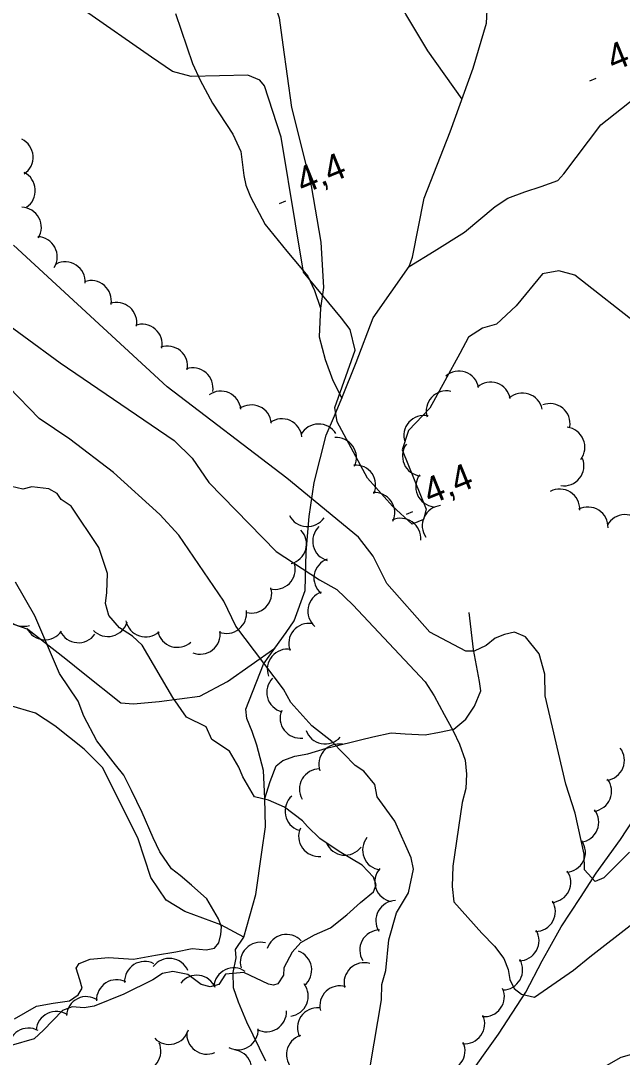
# Model space of a CAD drawing. Extents: x 362852 to 366875, y 5563573 to 5566479.
# Drawn here: x 364068.7 to 364158.5, y 5565324.6 to 5565479.3 of the extents above; entities that cross this region are included whole.
import ezdxf

# ---------------------------------------------------------------- set-up
doc = ezdxf.new("R2010")
doc.units = 0
for name, color, linetype in [('Niveau 1', 7, 'Continuous'), ('Niveau 2', 7, 'Continuous'), ('Niveau 22', 7, 'Continuous'), ('Niveau 3', 7, 'Continuous'), ('Niveau 44', 7, 'Continuous'), ('Niveau 7', 7, 'Continuous')]:
    doc.layers.add(name, color=color, linetype=linetype)

msp = doc.modelspace()

# ---------------------------------------------------------------- linework, layer by layer
at = {"layer": 'Niveau 1'}
for points in [[(364120.92, 5565323.43), (364122.56, 5565333.11), (364122.6, 5565335.4), (364123.21, 5565337.53), (364123.67, 5565342.07), (364124.81, 5565346.1), (364126.58, 5565349.09), (364127.32, 5565352.65), (364127, 5565354.32), (364124.54, 5565359.8), (364121.92, 5565363.44), (364121.55, 5565365.26), (364119.93, 5565367.25), (364118.62, 5565368.14), (364115.12, 5565371.7), (364112.17, 5565374.03), (364109.04, 5565377.53), (364107.94, 5565379.52), (364100.83, 5565388.92), (364099.05, 5565392.64), (364092.32, 5565402.51), (364089.49, 5565405.58), (364082.59, 5565411.87), (364076.04, 5565416.85), (364071.46, 5565419.94), (364066.94, 5565424.63)], [(364124.41, 5565287.96), (364124.93, 5565289.57), (364126.67, 5565294.45), (364127.91, 5565296.91), (364129.36, 5565298.57), (364130.31, 5565299.55), (364133.54, 5565305.42), (364135.12, 5565307.27), (364138.92, 5565309.96), (364142.25, 5565311.27), (364144.51, 5565313.16), (364146.81, 5565314.36), (364147.72, 5565315.51), (364148.63, 5565315.94), (364152.51, 5565320.76), (364153.91, 5565322.06), (364158.31, 5565324.57), (364165.11, 5565326.53)]]:
    msp.add_lwpolyline(points, dxfattribs=at)
at = {"layer": 'Niveau 2'}
for points in [[(364159.55, 5565355.17), (364155.73, 5565351.34), (364154.44, 5565350.81), (364152.86, 5565352.55), (364152.79, 5565354.9), (364151.44, 5565361), (364150.06, 5565365.33), (364146.98, 5565378.5), (364146.92, 5565381.74), (364146.07, 5565384.78), (364144.03, 5565387.34), (364142.38, 5565388.04), (364140.9, 5565387.68), (364139.5, 5565387.11), (364138.18, 5565386.06), (364136.4, 5565385.21), (364135.15, 5565385.2), (364129.77, 5565388.01), (364123.33, 5565395.29), (364121.3, 5565399.36), (364119.14, 5565402.23), (364108.45, 5565411.04), (364090.56, 5565424.67), (364067.63, 5565445.8)], [(364063.74, 5565436.2), (364074.59, 5565428.23), (364091.63, 5565416.66), (364094.32, 5565414), (364096.79, 5565410.37), (364106.83, 5565400.07), (364113.29, 5565395.82), (364115.87, 5565394.38), (364118.28, 5565392.11), (364129.05, 5565380.6), (364130.39, 5565378.52), (364131.89, 5565375.75), (364133.25, 5565373.3), (364134.19, 5565371.3), (364135.04, 5565368.9), (364135.24, 5565366.85), (364135.13, 5565364.67), (364134.6, 5565362.57), (364133.2, 5565353.1), (364133.07, 5565350.04), (364133.36, 5565347.78), (364137.5, 5565343.09), (364139.42, 5565341.12), (364140.78, 5565339.3), (364141.43, 5565337.68), (364141.68, 5565336.16), (364142.35, 5565334.8), (364143.43, 5565333.99), (364145.36, 5565333.53), (364151.21, 5565337.56), (364153.64, 5565339.56), (364160.09, 5565344.59)], [(364083.46, 5565388.67), (364081.89, 5565390.51), (364081.38, 5565392.29), (364081.59, 5565393.94), (364081.67, 5565396.78), (364080.37, 5565400.65), (364076.27, 5565406.86), (364074.77, 5565407.85), (364074.15, 5565408.72), (364072.92, 5565409.42), (364070.36, 5565409.75), (364069.04, 5565409.37), (364067.34, 5565409.76), (364057.49, 5565421.38)], [(364067.8, 5565330.28), (364071.07, 5565332.18), (364073.55, 5565332.64), (364076.02, 5565332.97), (364077.28, 5565333.86), (364077.87, 5565334.85), (364077.53, 5565336.14), (364077.02, 5565337.87), (364077.43, 5565338.54), (364079.08, 5565339.21), (364081.83, 5565339.47), (364085.54, 5565339.19), (364088.84, 5565339.79), (364091.86, 5565340.28), (364094.32, 5565340.79), (364096.39, 5565340.58), (364097.65, 5565340.85), (364098.26, 5565341.66), (364098.56, 5565342.91), (364098.67, 5565344.01), (364098.24, 5565345.21), (364096.47, 5565348.22), (364094.22, 5565350.23), (364092.51, 5565351.71), (364091.24, 5565352.69), (364089.48, 5565355.21), (364088.5, 5565357.3), (364086.84, 5565361.11), (364085.26, 5565364.39), (364084.09, 5565366.66), (364082.86, 5565368.2), (364080.07, 5565371.8), (364078.12, 5565375.48), (364077.3, 5565377.71), (364074.52, 5565381.84), (364070.82, 5565390.47), (364067.95, 5565395.47)], [(364109.21, 5565340.25), (364110.52, 5565341.68), (364112.54, 5565342.83), (364114.92, 5565343.86), (364117.36, 5565345.81), (364119.42, 5565347.65), (364121.37, 5565349.26), (364121.76, 5565350.3), (364121.36, 5565351.44), (364119.69, 5565353.26), (364116.26, 5565355.28), (364113.36, 5565357.22), (364111.52, 5565359.02), (364110.79, 5565359.88), (364108.09, 5565361.92), (364105.67, 5565362.96), (364103.59, 5565363.44), (364101.85, 5565366.45), (364101.28, 5565367.87), (364099.86, 5565370.28), (364097.26, 5565372.02), (364096.38, 5565373.88), (364093.48, 5565375.34), (364091.4, 5565378.25), (364086.86, 5565386.11), (364085.4, 5565387.45), (364083.46, 5565388.67)], [(364109.21, 5565340.25), (364107.99, 5565337.89), (364107.94, 5565336.81), (364107.08, 5565335.52), (364106.43, 5565335.33), (364105.69, 5565335.47), (364102.01, 5565337.23), (364099.26, 5565336.96), (364098.3, 5565335.44), (364096.99, 5565335.07), (364095.66, 5565335.4), (364093.65, 5565336.93), (364091.42, 5565337.35), (364089.9, 5565337.07), (364088.43, 5565336.13), (364084.1, 5565333.98), (364079.7, 5565332.19), (364078.19, 5565331.94), (364076.39, 5565332.11), (364074.96, 5565331.53), (364072.13, 5565328.6), (364070.73, 5565327.3), (364067.31, 5565326.31)]]:
    msp.add_lwpolyline(points, dxfattribs=at)
at = {"layer": 'Niveau 22'}
for points in [[(364134.57, 5565467.62), (364129.45, 5565474.84), (364126.18, 5565480.29), (364120.27, 5565490.7), (364114.99, 5565497.09), (364112.39, 5565501.63), (364107.86, 5565511.42), (364102.92, 5565525.77), (364101.49, 5565533.31), (364101.83, 5565535.72), (364103.26, 5565542.86), (364103.01, 5565544.27), (364101.37, 5565550.35), (364100.43, 5565554.69), (364100.77, 5565556.78), (364101.53, 5565558.8), (364102.86, 5565563.69), (364102.91, 5565565.1), (364103.94, 5565566.91), (364108.75, 5565573.3), (364113.88, 5565584.31), (364114.87, 5565586.27)], [(364076.01, 5565570.5), (364075.83, 5565567.1), (364076.49, 5565560.05), (364078.35, 5565552.24), (364079.56, 5565545.67), (364081.42, 5565537.86), (364083.93, 5565532.08), (364086.33, 5565528.03), (364089.46, 5565519.54), (364092.91, 5565510.88), (364098.61, 5565499.93), (364104.42, 5565488.53), (364107.28, 5565479.75), (364107.85, 5565475.71), (364109.14, 5565466.36), (364112.07, 5565454.65), (364113.52, 5565446.25), (364113.89, 5565439.48), (364113.44, 5565436.4), (364113.34, 5565434.35), (364113.24, 5565432.11), (364114.15, 5565428.76), (364115.31, 5565425.58), (364116.62, 5565422.98)], [(364105.31, 5565323.98), (364102.45, 5565329.81), (364101.23, 5565332.79), (364100.49, 5565334.92), (364100.4, 5565337.23), (364100.87, 5565339.4), (364100.78, 5565340.64), (364102, 5565342.5), (364103.79, 5565348.88), (364104.7, 5565355.18), (364105.23, 5565358.97), (364105.13, 5565363.17), (364104.95, 5565367.37), (364103.97, 5565371.17), (364103.27, 5565373.18), (364102.46, 5565375.16), (364102.33, 5565376.53), (364104.96, 5565383.24), (364106.65, 5565385.62), (364108.35, 5565388), (364109.51, 5565389.73), (364111.16, 5565394.24), (364111.29, 5565399.99), (364111.76, 5565405.28), (364112.51, 5565410.39), (364114.3, 5565417.46), (364115.54, 5565420.31), (364116.62, 5565422.98), (364118.76, 5565428.31), (364121.32, 5565434.96), (364126.67, 5565442.63), (364127.17, 5565444.03), (364128.94, 5565452.82), (364132.81, 5565462.71), (364136.23, 5565472.24), (364138.2, 5565478.97), (364138.69, 5565488.74)], [(364126.67, 5565442.63), (364130.43, 5565444.93), (364134.94, 5565447.73), (364139.52, 5565451.56), (364141.39, 5565452.83), (364143.95, 5565453.76), (364146.38, 5565454.57), (364148.84, 5565455.45), (364149.74, 5565456.46), (364155.25, 5565463.76), (364160.5, 5565467.93), (364167.05, 5565471.56), (364168.87, 5565472.52), (364174.36, 5565475.98), (364175.69, 5565478.41), (364178.22, 5565483.29)], [(364091.81, 5565480.39), (364094.33, 5565472.93), (364095.52, 5565470.45), (364097.36, 5565466.99), (364100.36, 5565462.38), (364101.59, 5565459.8), (364101.99, 5565456.19), (364102.32, 5565454.75), (364103.02, 5565453.02), (364105.2, 5565448.88), (364108.43, 5565444.92), (364111.58, 5565441.19), (364112.58, 5565439.02), (364113.44, 5565436.4)], [(364062.02, 5565391.16), (364069.78, 5565388.46), (364075.46, 5565384.06), (364078.05, 5565381.97), (364083.66, 5565377.49), (364085.53, 5565377.35), (364089.37, 5565377.69), (364095.46, 5565378.47), (364099.58, 5565380.64), (364106.65, 5565385.62)], [(364105.13, 5565363.17), (364105.93, 5565365.71), (364106.82, 5565368.07), (364107.82, 5565368.88), (364109.64, 5565369.52), (364111.55, 5565369.87), (364114.33, 5565370.7), (364115.2, 5565370.89), (364119.44, 5565371.93), (364121.27, 5565372.39), (364123.97, 5565373.02), (364126.06, 5565372.84), (364129.06, 5565372.72), (364131.21, 5565373.08), (364133.32, 5565373.56), (364135.11, 5565375.06), (364136.44, 5565376.98), (364137.37, 5565379.28), (364137.15, 5565380.66), (364136.28, 5565385.43), (364135.63, 5565390.98)], [(364102, 5565342.5), (364098.58, 5565344.33), (364093.21, 5565346.34), (364090.43, 5565348.02), (364088.15, 5565351.4), (364086.25, 5565357.16), (364080.96, 5565367.78), (364078.21, 5565370.58), (364073.8, 5565374.03), (364070.94, 5565375.93), (364064.16, 5565377.9), (364060.41, 5565379.01), (364057.36, 5565381.16), (364054.49, 5565384.6), (364051.69, 5565388.65)], [(364104.64, 5565289.11), (364110.21, 5565293.57), (364116.31, 5565298.95), (364118.78, 5565301.52), (364122.36, 5565305.25), (364128.68, 5565313.54), (364134.91, 5565320.89), (364140.03, 5565327.99), (364144.1, 5565334.29), (364146.51, 5565338.94), (364147.4, 5565340.54), (364149.36, 5565344.04), (364152.24, 5565348.43), (364154.57, 5565352.03), (364158.2, 5565357.05), (364163.11, 5565364.61)]]:
    msp.add_lwpolyline(points, dxfattribs=at)
at = {"layer": 'Niveau 3'}
for p, q in [((364153.64, 5565470.37), (364154.6, 5565470.76)), ((364107.31, 5565452.03), (364108.27, 5565452.42)), ((364126.26, 5565405.65), (364127.22, 5565406.04))]:
    msp.add_line(p, q, dxfattribs=at)
at = {"layer": 'Niveau 44'}
for centre, start, end in [((364067.57, 5565458.95), 303.8962, 63.8742), ((364067.91, 5565453.96), 303.8962, 63.8742), ((364068.81, 5565448.47), 328.3589, 88.3369), ((364071.18, 5565444.07), 328.3589, 88.3369), ((364075.35, 5565440.32), 356.8135, 116.7915), ((364079.25, 5565437.52), 349.3105, 109.2884), ((364083.04, 5565434.26), 349.3105, 109.2884), ((364086.83, 5565431), 349.3105, 109.2884), ((364090.62, 5565427.74), 349.4935, 109.4714), ((364094.42, 5565424.49), 349.4935, 109.4714), ((364134.1, 5565424), 10.8423, 130.8203), ((364138.82, 5565422.36), 10.8423, 130.8203), ((364098.58, 5565421.02), 5.5854, 125.5634), ((364132.22, 5565421.05), 77.3792, 197.3572), ((364143.57, 5565420.74), 11.5864, 131.5643), ((364103.14, 5565418.96), 5.5854, 125.5634), ((364147.69, 5565419.15), 350.8539, 110.8319), ((364128.88, 5565417.37), 78.1561, 198.1341), ((364107.69, 5565416.89), 5.5854, 125.5634), ((364113.19, 5565416.11), 31.382, 151.36), ((364149.89, 5565415.64), 322.8922, 82.8702), ((364115.82, 5565414.08), 334.9018, 94.8797), ((364128.68, 5565414.33), 143.3327, 263.3107), ((364118.68, 5565409.98), 334.9018, 94.8797), ((364149.76, 5565412.88), 261.21, 21.1879), ((364130.66, 5565409.74), 143.3327, 263.3107), ((364121.54, 5565405.87), 334.9018, 94.8797), ((364149.13, 5565406.39), 357.6292, 117.6072), ((364131.63, 5565403.94), 95.2797, 215.2576), ((364153.35, 5565403.71), 357.6292, 117.6072), ((364111.5, 5565406.78), 206.3061, 326.284), ((364125.41, 5565402.03), 355.2253, 115.2033), ((364158.9, 5565402.58), 31.76, 151.7379), ((364115.29, 5565401.62), 133.9004, 253.8783), ((364108.36, 5565401.19), 283.7779, 43.7559), ((364115.47, 5565396.1), 109.5789, 229.5568), ((364106.69, 5565397.42), 255.1927, 15.1707), ((364103.17, 5565393.87), 255.1927, 15.1707), ((364069.12, 5565391.9), 167.5618, 287.5398), ((364114.56, 5565391.18), 109.5789, 229.5568), ((364099.42, 5565390.84), 248.3091, 8.2871), ((364081.72, 5565390.38), 223.9787, 343.9567), ((364087.36, 5565390.32), 191.8809, 311.8589), ((364072.36, 5565389.89), 204.9743, 324.9523), ((364077.34, 5565389.45), 204.9743, 324.9523), ((364092.11, 5565388.76), 191.8809, 311.8589), ((364095.5, 5565387.74), 248.3091, 8.2871), ((364111.71, 5565386.34), 80.2736, 200.2515), ((364108.51, 5565382.49), 80.2736, 200.2515), ((364108.43, 5565379.05), 135.3524, 255.3303), ((364110.43, 5565375.2), 157.419, 277.3969), ((364114.14, 5565374.33), 198.8421, 318.8201), ((364116.2, 5565368.33), 79.5353, 199.5133), ((364155.79, 5565368.89), 277.5691, 37.5471), ((364113.31, 5565364.6), 89.8313, 209.8093), ((364153.88, 5565364.27), 277.5691, 37.5471), ((364111.15, 5565361.3), 131.3313, 251.3092), ((364151.97, 5565359.65), 277.5691, 37.5471), ((364113.19, 5565357.54), 155.6943, 275.6722), ((364122.73, 5565355.5), 141.6404, 261.6184), ((364117.09, 5565357.73), 203.4596, 323.4375), ((364149.97, 5565355.17), 274.1433, 34.1212), ((364124.55, 5565350.77), 139.1795, 259.1574), ((364147.79, 5565350.67), 274.1433, 34.1212), ((364124.71, 5565344.95), 91.382, 211.3599), ((364145.49, 5565346.33), 270.8249, 30.8028), ((364122.31, 5565340.56), 91.382, 211.3599), ((364143.05, 5565341.96), 270.8249, 30.8028), ((364104.49, 5565338.72), 75.7269, 195.7049), ((364108.36, 5565339.9), 42.9494, 162.9273), ((364109.14, 5565337.58), 310.4122, 70.3901), ((364087.22, 5565335.86), 62.5146, 182.4925), ((364090.91, 5565336.32), 23.2324, 143.2103), ((364119.97, 5565335.68), 73.6505, 193.6284), ((364140.61, 5565337.6), 270.8249, 30.8028), ((364094.99, 5565333.8), 22.6243, 142.6023), ((364100.53, 5565334.9), 55.8369, 175.8149), ((364083.04, 5565333.14), 63.032, 183.0099), ((364108.63, 5565333.68), 277.2896, 37.2675), ((364116.35, 5565332.23), 73.6505, 193.6284), ((364137.88, 5565333.62), 264.1469, 24.1249), ((364078.53, 5565330.61), 56.1464, 176.1243), ((364074.04, 5565328.41), 56.1464, 176.1243), ((364105.38, 5565331.36), 242.3233, 2.3013), ((364113.03, 5565328.95), 86.059, 206.0369), ((364134.95, 5565329.57), 264.1469, 24.1249), ((364069.87, 5565325.91), 61.4208, 181.3987), ((364090.86, 5565329.48), 224.2281, 344.2061), ((364096.49, 5565328.02), 173.41, 293.388), ((364101.16, 5565328.68), 242.3233, 2.3013), ((364111.37, 5565324.94), 107.8748, 227.8527), ((364086.64, 5565325.5), 264.1786, 24.1565), ((364132.02, 5565325.52), 264.1469, 24.1249), ((364100.21, 5565322.7), 321.9579, 81.9359)]:
    msp.add_arc(centre, 3, start, end, dxfattribs=at)
at = {"layer": 'Niveau 7'}
for points in [[(364091.35, 5565471.75), (364088.24, 5565473.87), (364078.25, 5565480.83), (364075.22, 5565482.74), (364069.87, 5565488.85), (364062.53, 5565494.91), (364052.69, 5565500.55), (364048.82, 5565502.99), (364045.22, 5565505.68), (364041.94, 5565506.97), (364035.37, 5565515.98), (364033.75, 5565519.98), (364029.9, 5565524.83), (364027.1, 5565525.57), (364021.67, 5565525.99), (364018.92, 5565527.51), (364015.51, 5565531.91), (364011.98, 5565537.52), (364009.69, 5565542.26), (364009.01, 5565543.3)], [(364161.3, 5565433.59), (364151.41, 5565441.35), (364149.02, 5565442), (364146.59, 5565441.51), (364142.64, 5565436.74), (364139.73, 5565434.03), (364137.6, 5565433.41), (364135.52, 5565432.05), (364134.25, 5565429.64), (364129.76, 5565421.48), (364126.59, 5565418.16), (364125.64, 5565415.26), (364129.22, 5565406.41), (364128.84, 5565404.87), (364127.13, 5565404.17), (364124.17, 5565406.85), (364120.48, 5565411), (364115.94, 5565419.45), (364115.58, 5565421.57), (364118.63, 5565430.12), (364117.88, 5565433.21), (364116.56, 5565434.93), (364110.9, 5565441.79), (364109.74, 5565448.99), (364107.6, 5565461.93), (364105.12, 5565469.6), (364104.4, 5565470.44), (364102.59, 5565471.21), (364094.15, 5565471.02), (364091.35, 5565471.75)]]:
    msp.add_lwpolyline(points, dxfattribs=at)

# ---------------------------------------------------------------- texts
at = {"layer": 'Niveau 3'}
for s, p in [('4,8  ', (364157.15, 5565471.73)), ('4,4  ', (364110.82, 5565453.39)), ('4,4  ', (364129.77, 5565407.01))]:
    msp.add_text(s, height=3.93, rotation=22.09, dxfattribs=at).set_placement(p)

doc.saveas('drawing.dxf')
